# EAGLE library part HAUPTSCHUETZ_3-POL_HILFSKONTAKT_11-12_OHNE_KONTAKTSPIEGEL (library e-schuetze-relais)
Hauptschütz mit 3 Schließern, 1 Öffner ohne Kontaktspiegel
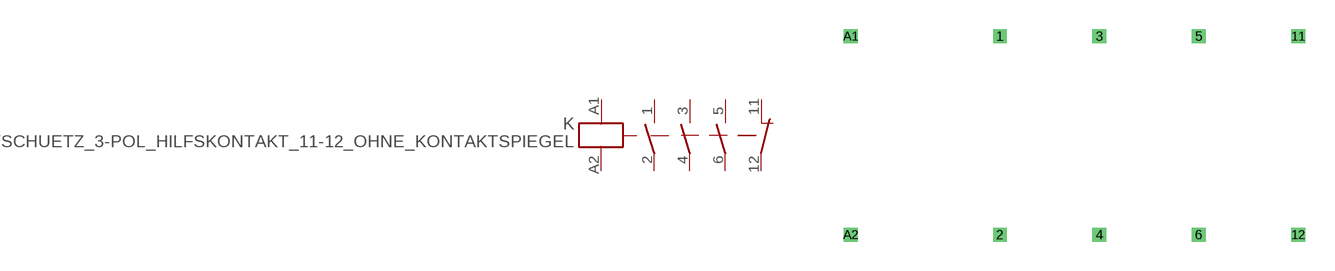
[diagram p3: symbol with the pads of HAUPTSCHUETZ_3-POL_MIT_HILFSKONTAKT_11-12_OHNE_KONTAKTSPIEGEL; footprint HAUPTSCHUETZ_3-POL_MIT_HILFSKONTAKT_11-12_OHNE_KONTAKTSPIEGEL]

Designator prefix K

## HAUPTSCHUETZ_3-POL_HILFSKONTAKT_11-12_OHNE_KONTAKTSPIEGEL  [HAUPTSCHUETZ_3-POL_MIT_HILFSKONTAKT_11-12_OHNE_KONTAKTSPIEGEL]
1  1  pas
2  2  pas
3  3  pas
4  4  pas
5  5  pas
6  6  pas
11  21  pas
12  22  pas
A1  A1  in
A2  A2  in

## Footprint HAUPTSCHUETZ_3-POL_MIT_HILFSKONTAKT_11-12_OHNE_KONTAKTSPIEGEL (pad centres in mm)
Dummy
drill 0.2 pad 0.6 square: 1 7.62,5.08; 2 7.62,-5.08; 3 12.7,5.08; 4 12.7,-5.08; 5 17.78,5.08; 6 17.78,-5.08; 11 22.86,5.08; 12 22.86,-5.08; A1 0,5.08; A2 0,-5.08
